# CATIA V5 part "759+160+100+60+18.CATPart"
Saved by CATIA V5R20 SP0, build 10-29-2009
Part number: 759+160+100+60+18
Revision: TUTTO
Definition: NON CONOSCIUTO
Nomenclature: 759+160+100+60+18
Source: Unknown
Bounding box of the stored display mesh (mm): x -80 to 80, y -50 to 50, z 0 to 60
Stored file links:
  C:\Users\Utente\Desktop\IO LAVORO\3D X SITO CF\X 3D SITO CF 27-09-2020\759\759+160+100+60+18.CATPart
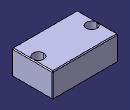
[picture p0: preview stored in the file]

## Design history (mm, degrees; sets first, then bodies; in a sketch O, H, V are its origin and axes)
Body1 "Importato1" (main body)
  Solid1: solid without history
